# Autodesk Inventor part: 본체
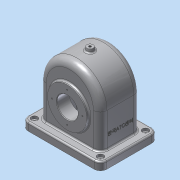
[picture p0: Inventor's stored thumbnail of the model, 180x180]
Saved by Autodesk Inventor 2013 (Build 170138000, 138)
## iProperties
Created: 2016-10
Part Number: 본체
Material: 알루미늄 6061
Document SubType Name: Modeling
Designer: Administrator
Mass: 1165.05 g
Surface Area: 1200.05 cm^2
Volume: 429.908 cm^3
Density: 2.71 g/cm^3
Author: Administrator
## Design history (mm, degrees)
sketch "스케치1"
  geometry: L1 (-43, 75)-(43, 75); L2 (55, 63)-(55, -63); L3 (43, -75)-(-43, -75); L4 (-55, -63)-(-55, 63); A1 r 12 centre (-43, 63) between (-43, 75) and (-55, 63); A2 r 12 centre (43, 63) between (55, 63) and (43, 75); A3 r 12 centre (43, -63) between (43, -75) and (55, -63); A4 r 12 centre (-43, -63) between (-55, -63) and (-43, -75); 6 further points
  constraints: 8 end point, 8 point on circle, 8 tangent, 6 point on line, 4 centre point, 3 equal radius, 2 midpoint, 2 parallel, 1 horizontal, 1 horizontal alignment, 1 perpendicular, 1 vertical alignment
  dimensions: "d0" = 110 distance of point (-55, 75) point (55, 75); "d2" = 150 distance of point (55, 75) point (55, -75); "d3" = 12 radius of A1
extrude "돌출1" new body sketch "스케치1" distance "d4" = 15; taper "d5" = 0 deg
sketch "스케치2"
  geometry: L1 (63, 15)-(-63, 15) reference; L2 (-63, 15)-(-75, 15) reference; L3 (75, 15)-(63, 15) reference; L4 (-58, 15)-(-58, 80); L5 (58, 80)-(58, 15); A1 r 58 centre (0, 80) between (58, 80) and (-58, 80); 1 further point
  constraints: 4 end point, 2 perpendicular, 2 point on circle, 2 point on line, 2 tangent, 1 centre point, 1 vertical alignment
  dimensions: "d6" = 80 distance of point (0, 0) A1.centre; "d7" = 58 radius of A1
extrude "돌출2" join sketch "스케치2" stored distance "d8" = 77; taper "d9" = 0 deg
sketch "스케치3"
  geometry: L1 (58, 80)-(58, 15) reference; L2 (-58, 15)-(-58, 80) reference; L3 (-63, 0)-(63, 0) reference; L4 (-52, 0)-(-52, 80); L5 (52, 80)-(52, 0); A1 r 58 centre (0, 80) between (58, 80) and (-58, 80) reference; A2 r 52 centre (0, 80) between (52, 80) and (-52, 80); 1 further point
  constraints: 4 end point, 2 point on circle, 2 point on line, 1 centre point
  dimensions: "d10" = 6 distance between parallel lines of L1 L5; "d11" = 6 distance between parallel lines of L2 L4; "d12" = 6 radial gap between concentric circles of A1 A2
extrude "돌출3" cut sketch "스케치3" stored distance "d13" = 67; taper "d14" = 0 deg
sketch "스케치4"
  geometry: L1 (0, 63)-(0, -63) reference; C1 r 31 at (-65, 0); 2 further points
  constraints: 1 centre point, 1 horizontal alignment, 1 midpoint
  dimensions: "d15" = 62 diameter of C1; "d17" = 65 distance from line of L1 C1.centre
extrude "돌출4" join sketch "스케치4" distance "d18" = 10; taper "d19" = 0 deg
sketch "스케치5"
  geometry: C1 r 37.5 at (65, 0); 1 further point
  constraints: 1 centre point, 1 horizontal alignment
  dimensions: "d20" = 75 diameter of C1; "d22" = 65 distance of C1.centre point (0, 0)
extrude "돌출5" join sketch "스케치5" distance "d23" = 5; taper "d24" = 0 deg
node "작업 평면1"
sketch "스케치6"
  geometry: C1 r 6 at (0, 0); 1 further point
  constraints: 1 centre point, 1 coincident
  dimensions: "d26" = 12 diameter of C1
extrude "돌출6" join sketch "스케치6" distance "d28" = 10; taper "d29" = 10 deg
sketch "스케치7"
  geometry: L1 (43.5, 27.5)-(43.5, 102.5) reference; L2 (33.5, 80)-(33.5, 132) reference; L3 (33.5, 0)-(33.5, 80) reference; L4 (43.5, 65)-(19.5, 65); L5 (19.5, 65)-(19.5, 93); L6 (19.5, 93)-(33.5, 104.747); L7 (33.5, 104.747)-(33.5, 65); 1 further point
  constraints: 8 end point, 3 point on line, 2 perpendicular, 1 midpoint
  dimensions: "d30" = 56 diameter of L5.end L4; "d32" = 50 deg angle of L6 L5; "d34" = 24 distance between parallel lines of L5 L1
revolve "회전1" sketch "스케치7" stored, may be unused: angle "d35" = 90 deg
hole "구멍1" diameter "d38" = 40; stored, may be unused: countersink angle "d42" = 90 deg, drill point angle "d44" = 118 deg; dims "d36" = 10, "d37" = 10, "d39" = 6, "d40" = 4, "d41" = 2, "d43" = 8
hole "구멍2" diameter "d47" = 4.459; stored, may be unused: countersink angle "d51" = 90 deg, drill point angle "d53" = 118 deg; dims "d45" = 10, "d46" = 10, "d48" = 6, "d49" = 4, "d50" = 2, "d52" = 8
hole "구멍3" diameter "d56" = 5; stored, may be unused: countersink angle "d60" = 90 deg, drill point angle "d62" = 118 deg; dims "d54" = 10, "d55" = 10, "d57" = 6, "d58" = 12, "d59" = 5, "d61" = 8
hole "구멍4" diameter "d65" = 5; stored, may be unused: countersink angle "d69" = 90 deg, drill point angle "d71" = 118 deg; dims "d63" = 10, "d64" = 10, "d66" = 6, "d67" = 12, "d68" = 5, "d70" = 8
hole "구멍5" diameter "d74" = 5; stored, may be unused: countersink angle "d78" = 90 deg, drill point angle "d80" = 118 deg; dims "d72" = 10, "d73" = 10, "d75" = 6, "d76" = 12, "d77" = 5, "d79" = 8
hole "구멍6" diameter "d83" = 5; stored, may be unused: countersink angle "d87" = 90 deg, drill point angle "d89" = 118 deg; dims "d81" = 10, "d82" = 10, "d84" = 6, "d85" = 12, "d86" = 5, "d88" = 8
sketch "스케치8"
  geometry: C1 r 20 at (0, 0) reference; 2 further points
  constraints: 1 horizontal alignment
  dimensions: "d90" = 26 distance of point (26, 0) C1.centre
hole "구멍7" sketch "스케치8" at (26, 0) diameter "d91" = 2.459; stored, may be unused: countersink angle "d95" = 90 deg, drill point angle "d97" = 118 deg; dims "d92" = 6, "d93" = 12, "d94" = 5, "d96" = 8
sketch "스케치9"
  geometry: C1 r 20 at (0, 0) reference; 2 further points
  constraints: 1 horizontal alignment
  dimensions: "d101" = 29 distance of C1.centre point (-29, 0)
hole "구멍8" sketch "스케치9" at (-29, 0) diameter "d102" = 2.459; stored, may be unused: countersink angle "d106" = 90 deg, drill point angle "d108" = 118 deg; dims "d103" = 6, "d104" = 12, "d105" = 5, "d107" = 8
sketch "스케치10"
  geometry: 2 further points
  constraints: 1 vertical alignment, 1 other
  dimensions: "d112" = 40 distance of point (38.5, -15) point (38.5, 25)
feature "엠보싱1" sketch "스케치10" dims "d0" = 110, "d2" = 150, "d3" = 12, "d6" = 80, "d7" = 58, "d113" = 0.5, "d114" = 0
fillet "모깎기1" dims "d115" = 13
fillet "모깎기2" dims "d116" = 8
fillet "모깎기3" dims "d117" = 3
fillet "모깎기4" dims "d118" = 3
fillet "모깎기5" dims "d119" = 3
fillet "모깎기6" dims "d120" = 3
chamfer "모따기1" distance "d121" = 1; stored, may be unused: second distance "d122" = 2, angle "d123" = 45 deg
node "솔리드1"
pattern_circular "원형 패턴1" dims angle "d99" = 360 deg
pattern_circular "원형 패턴2" dims angle "d110" = 360 deg
other parameters: "d25" = 144
